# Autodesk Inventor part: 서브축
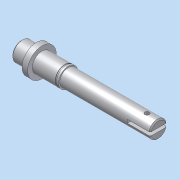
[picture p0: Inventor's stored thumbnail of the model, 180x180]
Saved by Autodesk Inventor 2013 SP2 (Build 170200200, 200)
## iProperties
Company: 한국ATC센터
Created: 2014-12
Part Number: 서브축
Document SubType Name: Modeling
Designer: KYOUNG IL JANG
Density: 1 g/cm^3
Mass: 23.2871 g
Surface Area: 76.512 cm^2
Volume: 23.2871 cm^3
Material: 일반
Author: KYOUNG IL JANG
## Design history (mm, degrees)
sketch "스케치1"
  geometry: L1 (0, 0)-(120, 0); L2 (0, 0)-(0, 7.5); L3 (1, 8.5)-(13, 8.5); L4 (13, 8.5)-(13, 12.5); L5 (13, 12.5)-(18, 12.5); L6 (18, 12.5)-(18, 8.5); L7 (18, 8.5)-(41, 8.5); L8 (120, 7.5)-(120, 0); L9 (0, 7.5)-(1, 8.5); L10 (41, 8.5)-(41, 7.5); L11 (41, 7.5)-(120, 7.5); 1 further point
  constraints: 22 end point, 3 parallel, 3 perpendicular, 2 collinear, 2 point on line, 2 vertical, 1 horizontal
  dimensions: "d0" = 5 distance of L4.end L5.end; "d1" = 17 diameter of L7 L1; "d2" = 13 distance of point (0, 8.5) L3.end; "d3" = 25 diameter of L5 L1; "d4" = 120 distance of L1.start L1.end; "d5" = 1 distance of L2.end point (0, 8.5); "d6" = 1 distance of L3.start point (0, 8.5) (= d5); "d15" = 15 diameter of L11 L1; "d16" = 23 distance of L6.end L7.end
revolve "회전1" sketch "스케치1" stored, may be unused: angle "d9" = 90 deg
node "작업 평면1"
sketch "스케치2"
  geometry: L1 (11.5, 12.5)-(11.5, -12.5) reference; L2 (-3, 2.5)-(6, 2.5); L3 (6, -2.5)-(-3, -2.5); A1 r 2.5 centre (6, 0) between (6, -2.5) and (6, 2.5); A2 r 2.5 centre (-3, 0) between (-3, 2.5) and (-3, -2.5); 1 further point
  constraints: 4 end point, 4 point on circle, 4 tangent, 2 centre point, 1 horizontal alignment, 1 parallel, 1 perpendicular
  dimensions: "d10" = 5 distance between parallel lines of L3 L2; "d11" = 14 dimension on A1 A2; "d12" = 3 distance edge to line of A1 L1
extrude "돌출1" cut sketch "스케치2" distance "d13" = 3; taper "d14" = 0 deg
sketch "스케치3"
  geometry: L1 (18, -12.5)-(18, 12.5) reference; L2 (13, -12.5)-(13, 12.5) reference; L3 (18, 8.5)-(41, 8.5) reference; L4 (38, 8.5)-(39.15, 8.5); L5 (39.15, 8.5)-(39.15, 8.1); L6 (39.15, 8.1)-(38, 8.1); L7 (38, 8.1)-(38, 8.5); L8 (-24, 0)-(144, 0) reference; 1 further point
  constraints: 8 end point, 2 parallel, 1 horizontal, 1 perpendicular, 1 point on line
  dimensions: "d17" = 20 distance between parallel lines of L7 L1; "d18" = 1.15 distance of L5.end L6.end; "d19" = 8.1 distance between parallel lines of L6 L8
revolve "회전2" sketch "스케치3" stored, may be unused: angle "d20" = 90 deg
chamfer "모따기1" distance "d21" = 1; stored, may be unused: second distance "d22" = 2, angle "d23" = 45 deg
sketch "스케치4"
  geometry: L1 (-120, 1.5)-(-100, 1.5); L2 (-100, 1.5)-(-100, -1.5); L3 (-100, -1.5)-(-120, -1.5); L4 (-120, -1.5)-(-120, 1.5); L5 (-120, -6.5)-(-120, 6.5) reference; 2 further points
  constraints: 8 end point, 2 parallel, 1 collinear, 1 horizontal, 1 horizontal alignment, 1 midpoint, 1 perpendicular
  dimensions: "d24" = 3 distance between parallel lines of L3 L1; "d25" = 20 distance of L2.end L3.end
extrude "돌출2" cut sketch "스케치4" stored distance "d26" = 10; taper "d27" = 0 deg
sketch "스케치5"
  geometry: L1 (120, 6.325)-(120, -6.325) reference; C1 r 2 at (110, 0); 1 further point
  constraints: 1 centre point, 1 horizontal alignment
  dimensions: "d28" = 4 diameter of C1; "d29" = 10 distance from line of L1 C1.centre
extrude "돌출3" cut sketch "스케치5" stored distance "d30" = 10; taper "d31" = 0 deg
node "솔리드1"
node "투영된 루프1"
